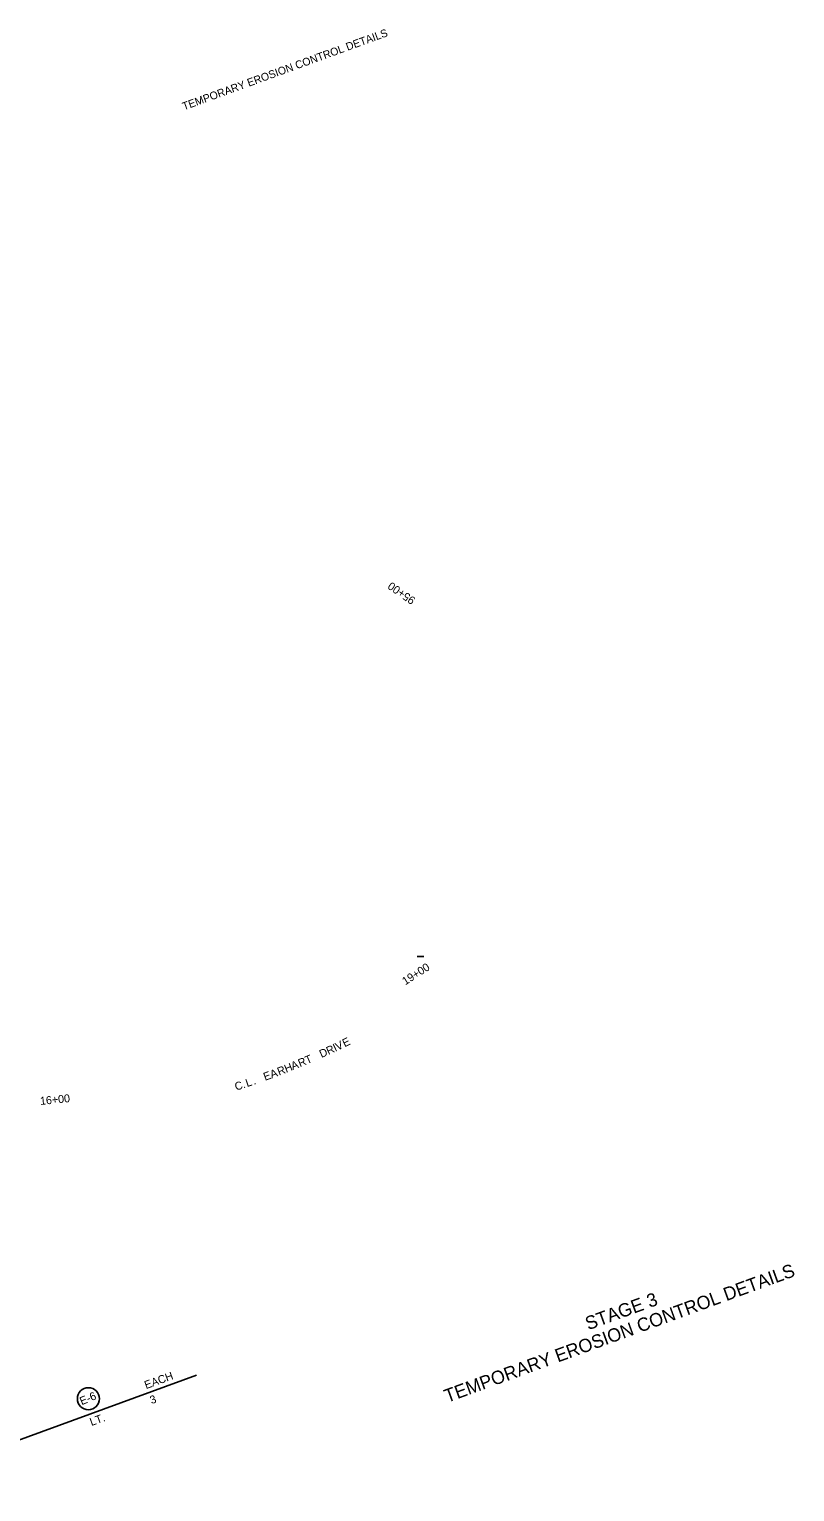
# Model space of a CAD drawing. Extents: x 1710782 to 1712392, y 548480 to 549912.
# Drawn here: x 1711817 to 1712392, y 548815 to 549912 of the extents above; entities that cross this region are included whole.
import ezdxf

# ---------------------------------------------------------------- set-up
doc = ezdxf.new("R2010")
doc.units = 0
for name, color, linetype in [('R_Contours', 7, 'Continuous'), ('R_Horz Alg', 7, 'Continuous'), ('R_Horz Alg Annot', 7, 'Continuous'), ('R_Proposed Const Limits_Fill', 7, 'Continuous')]:
    doc.layers.add(name, color=color, linetype=linetype)

msp = doc.modelspace()

# ---------------------------------------------------------------- linework, layer by layer
at = {"layer": 'R_Contours'}
msp.add_line((1712108.3, 549216.6), (1712113.4, 549216.6), dxfattribs=at)
at = {"layer": 'R_Horz Alg Annot'}
msp.add_line((1711702.8, 548815.2), (1711942.8, 548902.6), dxfattribs=at)
at = {"layer": 'R_Proposed Const Limits_Fill'}
msp.add_circle((1711861.6, 548885), 8.26, dxfattribs=at)

# ---------------------------------------------------------------- texts
at = {"layer": 'R_Contours'}
for s, rotation, p in [('95+00', 145.2214, (1712107.5, 549485.1)), ('19+00', 32.6088, (1712099.4, 549195)), ('16+00', 5.6088, (1711825.6, 549105.3))]:
    msp.add_text(s, height=6, rotation=rotation, dxfattribs=at).set_placement(p)
at = {"layer": 'R_Horz Alg'}
msp.add_text('TEMPORARY EROSION CONTROL DETAILS', height=5.862, rotation=20, dxfattribs=at).set_placement((1711933.3, 549851.2))
at = {"layer": 'R_Horz Alg Annot'}
for s, height, rotation, p in [('E', 6, 26.0441, (1712053.9, 549148.6)), ('D', 6, 24.3096, (1712036.5, 549140.5)), ('R', 6, 24.8223, (1712041.7, 549142.8)), ('I', 6, 25.3349, (1712046.8, 549145.2)), ('V', 6, 25.5144, (1712048.6, 549146)), ('R', 6, 21.1953, (1712004.7, 549127.3)), ('H', 6, 21.7079, (1712010, 549129.4)), ('A', 6, 22.1949, (1712015, 549131.4)), ('R', 6, 22.7247, (1712020.4, 549133.6)), ('T', 6, 23.2373, (1712025.7, 549135.8)), ('C', 6, 18.1065, (1711972.5, 549116)), ('L', 6, 18.8841, (1711980.7, 549118.7)), ('E', 6, 20.1785, (1711994.2, 549123.4)), ('A', 6, 20.6655, (1711999.2, 549125.2)), ('.', 6, 18.6192, (1711977.9, 549117.7)), ('.', 6, 19.3711, (1711985.8, 549120.4)), ('TEMPORARY EROSION CONTROL DETAILS', 10, 20, (1712130.8, 548881.9)), ('STAGE 3', 10, 20, (1712236.6, 548936.3)), ('EACH', 6, 20, (1711904.9, 548892.2)), ('3', 6, 20, (1711909, 548880.9)), ('LT. ', 6, 20, (1711863.9, 548864.5))]:
    msp.add_text(s, height=height, rotation=rotation, dxfattribs=at).set_placement(p)
at = {"layer": 'R_Proposed Const Limits_Fill'}
msp.add_text('E-6 ', height=6, rotation=22.7601, dxfattribs=at).set_placement((1711856.6, 548880.1))

doc.saveas('drawing.dxf')
